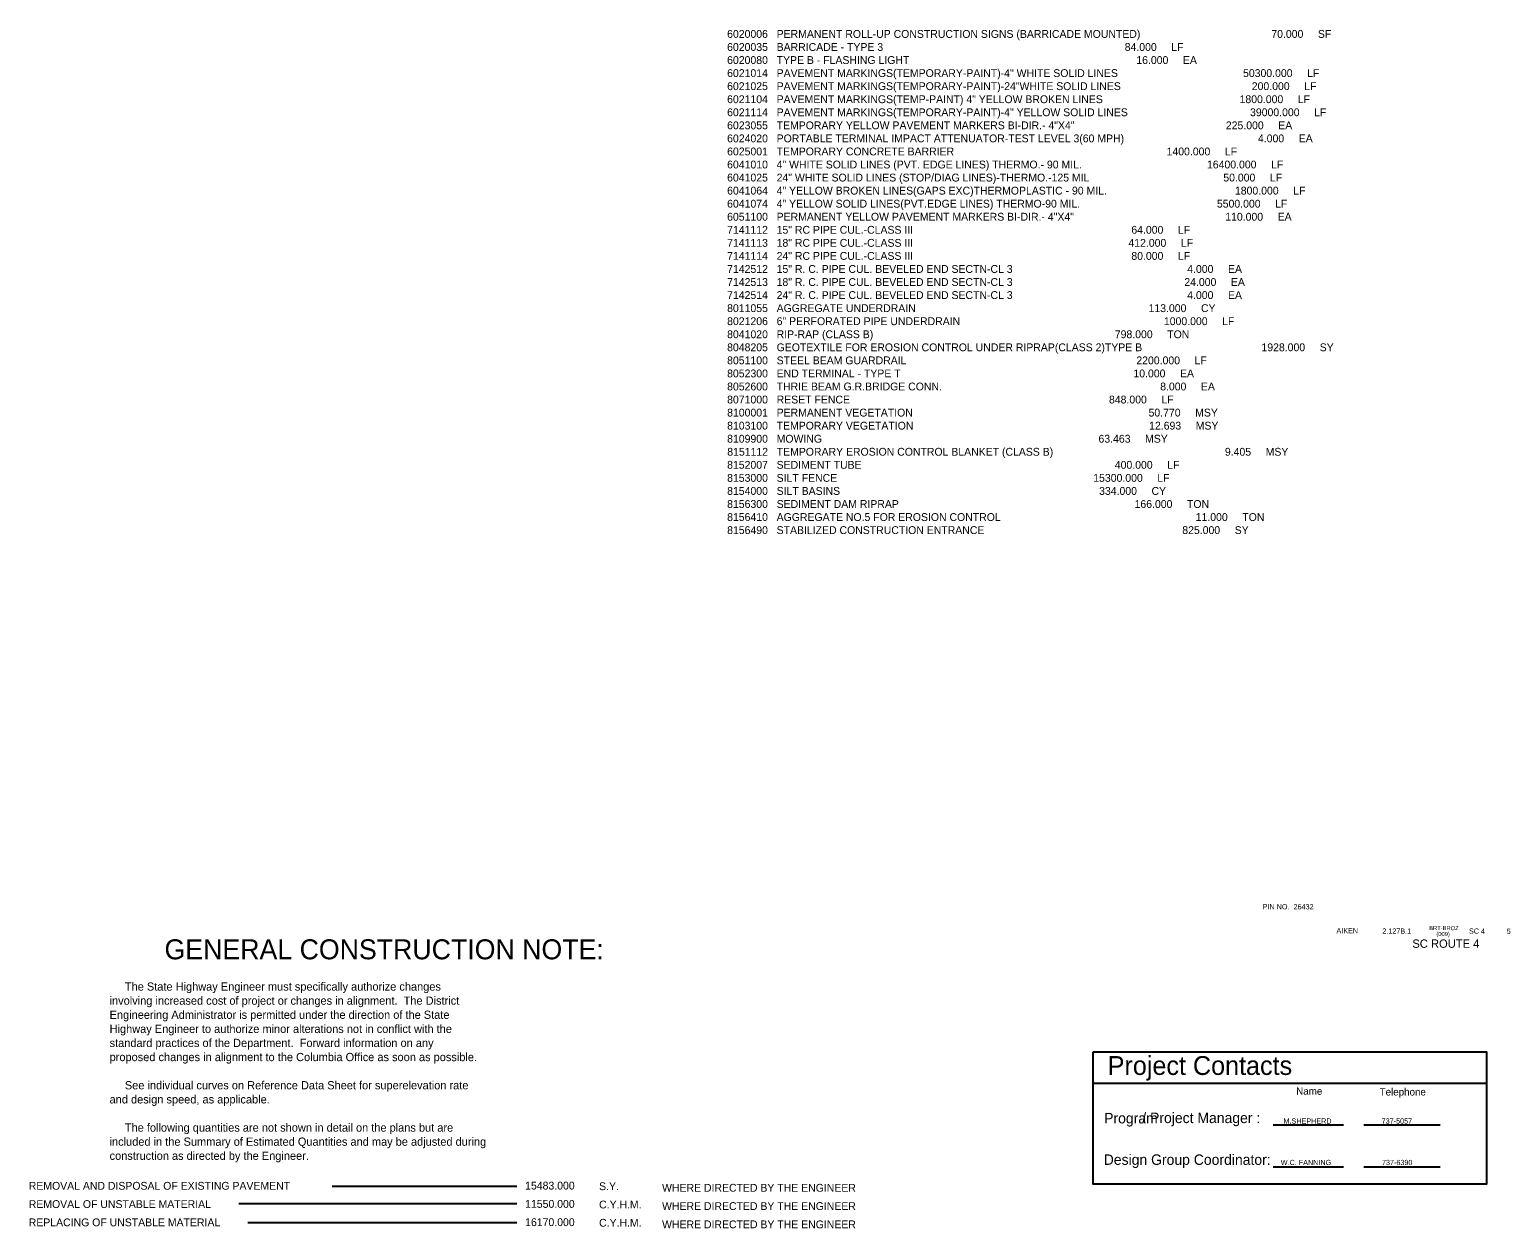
# Model space of a CAD drawing. Extents: x 17139 to 21295, y 12843 to 18076.
# Drawn here: x 17433 to 18851, y 14313 to 15461 of the extents above; entities that cross this region are included whole.
import ezdxf

# ---------------------------------------------------------------- set-up
doc = ezdxf.new("R2010")
doc.units = 0
for name, color, linetype in [('Level 1', 7, 'Continuous'), ('Level 2', 7, 'Continuous'), ('Level 23', 7, 'Continuous'), ('Level 27', 7, 'Continuous'), ('Level 3', 7, 'Continuous')]:
    doc.layers.add(name, color=color, linetype=linetype)

msp = doc.modelspace()

# ---------------------------------------------------------------- linework, layer by layer
at = {"layer": 'Level 2'}
for p, q in [((18451.3, 14452.2), (18827.7, 14452.2)), ((18623.4, 14412.2), (18690.8, 14412.2)), ((18710.2, 14412.2), (18783.3, 14412.2)), ((18623.4, 14372.2), (18690.8, 14372.2)), ((18710.2, 14372.2), (18783.3, 14372.2))]:
    msp.add_line(p, q, dxfattribs=at)
msp.add_lwpolyline([(18451.3, 14482.2), (18827.7, 14482.2), (18827.7, 14355.6), (18451.3, 14355.6)], close=True, dxfattribs=at)
at = {"layer": 'Level 23'}
for p, q in [((17722.5, 14353.7), (17899.3, 14353.7)), ((17633, 14337), (17899.3, 14337)), ((17641.7, 14318.9), (17899.3, 14318.9))]:
    msp.add_line(p, q, dxfattribs=at)

# ---------------------------------------------------------------- texts
at = {"layer": 'Level 1'}
for s, p in [('6020006   PERMANENT ROLL-UP CONSTRUCTION SIGNS (BARRICADE MOUNTED)                                             70.000     SF', (18100.7, 15452.9)), ('6020035   BARRICADE - TYPE 3                                                                                   84.000     LF', (18100.7, 15440.4)), ('6020080   TYPE B - FLASHING LIGHT                                                                              16.000     EA', (18100.7, 15427.9)), ('6021014   PAVEMENT MARKINGS(TEMPORARY-PAINT)-4" WHITE SOLID LINES                                           50300.000     LF', (18100.7, 15415.4)), ('6021025   PAVEMENT MARKINGS(TEMPORARY-PAINT)-24"WHITE SOLID LINES                                             200.000     LF', (18100.7, 15402.9)), ('6021104   PAVEMENT MARKINGS(TEMP-PAINT) 4" YELLOW BROKEN LINES                                               1800.000     LF', (18100.7, 15390.4)), ('6021114   PAVEMENT MARKINGS(TEMPORARY-PAINT)-4" YELLOW SOLID LINES                                          39000.000     LF', (18100.7, 15377.9)), ('6023055   TEMPORARY YELLOW PAVEMENT MARKERS BI-DIR.- 4"X4"                                                    225.000     EA', (18100.7, 15365.4)), ('6024020   PORTABLE TERMINAL IMPACT ATTENUATOR-TEST LEVEL 3(60 MPH)                                              4.000     EA', (18100.7, 15352.9)), ('6025001   TEMPORARY CONCRETE BARRIER                                                                         1400.000     LF', (18100.7, 15340.4)), ('6041010   4" WHITE SOLID LINES (PVT. EDGE LINES) THERMO.- 90 MIL.                                           16400.000     LF', (18100.7, 15327.9)), ('6041025   24" WHITE SOLID LINES (STOP/DIAG LINES)-THERMO.-125 MIL                                              50.000     LF', (18100.7, 15315.4)), ('6041064   4" YELLOW BROKEN LINES(GAPS EXC)THERMOPLASTIC - 90 MIL.                                            1800.000     LF', (18100.7, 15302.9)), ('6041074   4" YELLOW SOLID LINES(PVT.EDGE LINES) THERMO-90 MIL.                                               5500.000     LF', (18100.7, 15290.4)), ('6051100   PERMANENT YELLOW PAVEMENT MARKERS BI-DIR.- 4"X4"                                                    110.000     EA', (18100.7, 15277.9)), ('7141112   15" RC PIPE CUL.-CLASS III                                                                           64.000     LF', (18100.7, 15265.4)), ('7141113   18" RC PIPE CUL.-CLASS III                                                                          412.000     LF', (18100.7, 15252.9)), ('7141114   24" RC PIPE CUL.-CLASS III                                                                           80.000     LF', (18100.7, 15240.4)), ('7142512   15" R. C. PIPE CUL. BEVELED END SECTN-CL 3                                                            4.000     EA', (18100.7, 15227.9)), ('7142513   18" R. C. PIPE CUL. BEVELED END SECTN-CL 3                                                           24.000     EA', (18100.7, 15215.4)), ('7142514   24" R. C. PIPE CUL. BEVELED END SECTN-CL 3                                                            4.000     EA', (18100.7, 15202.9)), ('8011055   AGGREGATE UNDERDRAIN                                                                                113.000     CY', (18100.7, 15190.4)), ('8021206   6" PERFORATED PIPE UNDERDRAIN                                                                      1000.000     LF', (18100.7, 15177.9)), ('8041020   RIP-RAP (CLASS B)                                                                                   798.000     TON', (18100.7, 15165.4)), ('8048205   GEOTEXTILE FOR EROSION CONTROL UNDER RIPRAP(CLASS 2)TYPE B                                         1928.000     SY', (18100.7, 15152.9)), ('8051100   STEEL BEAM GUARDRAIL                                                                               2200.000     LF', (18100.7, 15140.4)), ('8052300   END TERMINAL - TYPE T                                                                                10.000     EA', (18100.7, 15127.9)), ('8052600   THRIE BEAM G.R.BRIDGE CONN.                                                                           8.000     EA', (18100.7, 15115.4)), ('8071000   RESET FENCE                                                                                         848.000     LF', (18100.7, 15102.9)), ('8100001   PERMANENT VEGETATION                                                                                 50.770     MSY', (18100.7, 15090.4)), ('8103100   TEMPORARY VEGETATION                                                                                 12.693     MSY', (18100.7, 15077.9)), ('8109900   MOWING                                                                                               63.463     MSY', (18100.7, 15065.4)), ('8151112   TEMPORARY EROSION CONTROL BLANKET (CLASS B)                                                           9.405     MSY', (18100.8, 15052.9)), ('8152007   SEDIMENT TUBE                                                                                       400.000     LF', (18100.7, 15040.4)), ('8153000   SILT FENCE                                                                                        15300.000     LF', (18100.7, 15027.9)), ('8154000   SILT BASINS                                                                                         334.000     CY', (18100.7, 15015.4)), ('8156300   SEDIMENT DAM RIPRAP                                                                                 166.000     TON', (18100.7, 15002.9)), ('8156410   AGGREGATE NO.5 FOR EROSION CONTROL                                                                   11.000     TON', (18100.7, 14990.4)), ('8156490   STABILIZED CONSTRUCTION ENTRANCE                                                                    825.000     SY', (18100.7, 14977.9))]:
    msp.add_text(s, height=7.5, dxfattribs=at).set_placement(p)
at = {"layer": 'Level 2'}
for s, height, p in [('Project Contacts', 18, (18465.1, 14460.1)), ('Name', 7, (18645.6, 14441.1)), ('Telephone', 7, (18725.5, 14440.4)), ('Program', 10, (18461.7, 14413.7)), ('/ Project Manager :', 10, (18498.2, 14414)), ('Design Group Coordinator:', 10, (18461.3, 14374))]:
    msp.add_text(s, height=height, dxfattribs=at).set_placement(p)
at = {"layer": 'Level 23'}
for s, p in [('REMOVAL AND DISPOSAL OF EXISTING PAVEMENT', (17432, 14350.2)), ('15483.000', (17907.3, 14350.4)), ('S.Y.', (17978.1, 14349.8)), ('WHERE DIRECTED BY THE ENGINEER', (18038.4, 14348.3)), ('REMOVAL OF UNSTABLE MATERIAL', (17432, 14332.7)), ('11550.000', (17907.3, 14332.9)), ('C.Y.H.M.', (17978.1, 14332.3)), ('WHERE DIRECTED BY THE ENGINEER', (18038.4, 14330.8)), ('REPLACING OF UNSTABLE MATERIAL', (17432, 14315.2)), ('16170.000', (17907.3, 14315.4)), ('C.Y.H.M.', (17978.1, 14314.8)), ('WHERE DIRECTED BY THE ENGINEER', (18038.4, 14313.3))]:
    msp.add_text(s, height=7.5, dxfattribs=at).set_placement(p)
at = {"layer": 'Level 27'}
for s, height, p in [('GENERAL CONSTRUCTION NOTE:', 19.125, (17562, 14570.8)), ('     The State Highway Engineer must specifically authorize changes', 7.875, (17509.4, 14540.8)), ('involving increased cost of project or changes in alignment.  The District', 7.875, (17509.4, 14527.3)), ('Engineering Administrator is permitted under the direction of the State', 7.875, (17509.4, 14513.8)), ('Highway Engineer to authorize minor alterations not in conflict with the', 7.875, (17509.4, 14500.3)), ('standard practices of the Department.  Forward information on any', 7.875, (17509.4, 14486.8)), ('proposed changes in alignment to the Columbia Office as soon as possible.', 7.875, (17509.4, 14473.3)), ('     See individual curves on Reference Data Sheet for superelevation rate', 7.875, (17509.4, 14446.3)), ('and design speed, as applicable.', 7.875, (17509.4, 14432.8)), ('     The following quantities are not shown in detail on the plans but are', 7.875, (17509.4, 14405.8)), ('included in the Summary of Estimated Quantities and may be adjusted during', 7.875, (17509.4, 14392.3)), ('construction as directed by the Engineer.', 7.875, (17509.4, 14378.8))]:
    msp.add_text(s, height=height, dxfattribs=at).set_placement(p)
at = {"layer": 'Level 3'}
for s, height, p in [('PIN NO.  26432', 5, (18613.5, 14618.6)), ('AIKEN', 5, (18684.1, 14595.7)), (' 2.127B.1', 5, (18726.1, 14595.3)), ('SC ROUTE 4', 8, (18756.8, 14581.8)), ('BRT-BROZ', 4, (18772.9, 14598.7)), ('(009)', 4, (18779.8, 14593)), ('SC 4', 5, (18811, 14595.3)), ('5', 5, (18847.2, 14595.1)), ('M.SHEPHERD', 5, (18633.4, 14413.5)), ('737-5057', 5, (18727.4, 14413.5)), ('W.C. FANNING', 5, (18630.8, 14373.8)), ('737-6390', 5, (18727.7, 14373.8))]:
    msp.add_text(s, height=height, dxfattribs=at).set_placement(p)

doc.saveas('drawing.dxf')
